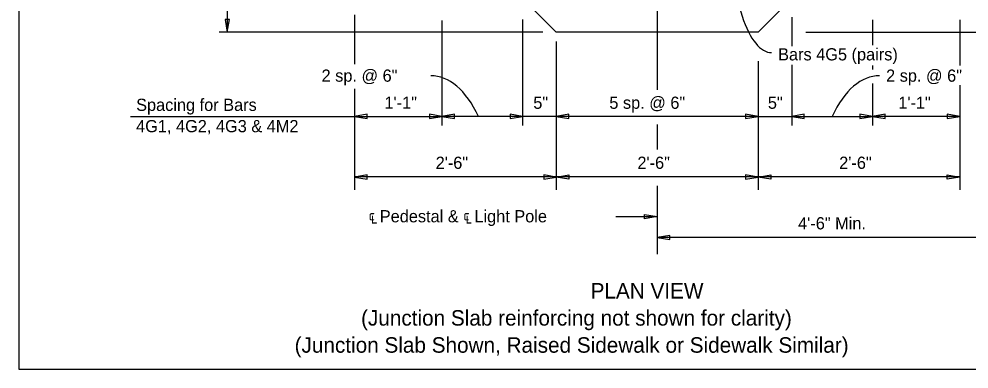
# Model space of a CAD drawing. Extents: x 0 to 54.1, y -0.5 to 22.5.
# Drawn here: x 0.01 to 11.78, y 1.54 to 5.88 of the extents above; entities that cross this region are included whole.
import ezdxf

# ---------------------------------------------------------------- set-up
doc = ezdxf.new("R2010")
doc.units = 0
for name, color, linetype in [('ActivePts-ConstElements', 7, 'Continuous'), ('CL_Major', 7, 'Continuous'), ('Dimension', 7, 'Continuous'), ('TextStructures', 7, 'Continuous'), ('WallConc', 7, 'Continuous')]:
    doc.layers.add(name, color=color, linetype=linetype)

msp = doc.modelspace()

# ---------------------------------------------------------------- linework, layer by layer
at = {"layer": 'ActivePts-ConstElements'}
msp.add_lwpolyline([(0.012, 1.54), (30.8, 1.54), (30.8, 21), (0.012, 21)], close=True, dxfattribs=at)
at = {"layer": 'CL_Major'}
for p, q in [((7.919, 15.044), (7.919, 5.002)), ((7.919, 4.572), (7.919, 4.26)), ((7.919, 3.812), (7.919, 2.962))]:
    msp.add_line(p, q, dxfattribs=at)
at = {"layer": 'Dimension'}
for p, q in [((2.593, 6.841), (2.593, 5.716)), ((4.169, 5.931), (4.169, 5.319)), ((9.586, 5.9), (9.586, 5.543)), ((5.252, 5.861), (5.252, 4.558)), ((6.252, 5.874), (6.252, 4.558)), ((10.586, 5.867), (10.586, 5.554)), ((11.669, 5.867), (11.669, 5.303)), ((6.503, 5.716), (2.493, 5.716)), ((9.762, 5.716), (15.801, 5.716)), ((6.669, 5.6), (6.669, 3.759)), ((9.169, 5.357), (9.169, 3.759)), ((9.586, 5.311), (9.586, 4.558)), ((10.586, 5.3), (10.586, 5.252)), ((10.586, 5.08), (10.586, 4.558)), ((4.169, 5.013), (4.169, 3.759)), ((11.669, 5.06), (11.669, 3.759)), ((1.394, 4.671), (4.169, 4.671)), ((4.169, 4.671), (5.252, 4.671)), ((6.252, 4.671), (5.252, 4.671)), ((6.669, 4.671), (6.252, 4.671)), ((9.169, 4.671), (6.669, 4.671)), ((9.169, 4.671), (9.586, 4.671)), ((9.586, 4.671), (10.586, 4.671)), ((11.669, 4.671), (10.586, 4.671)), ((11.669, 3.921), (4.169, 3.921)), ((7.408, 3.43), (7.919, 3.43)), ((12.419, 3.171), (7.919, 3.171))]:
    msp.add_line(p, q, dxfattribs=at)
for points in [[(2.593, 5.716), (2.619, 5.872), (2.566, 5.872)], [(4.169, 4.671), (4.325, 4.644), (4.325, 4.697)], [(5.252, 4.671), (5.096, 4.697), (5.096, 4.644)], [(5.252, 4.671), (5.409, 4.644), (5.409, 4.697)], [(6.252, 4.671), (6.096, 4.697), (6.096, 4.644)], [(6.669, 4.671), (6.825, 4.644), (6.825, 4.697)], [(9.169, 4.671), (9.013, 4.697), (9.013, 4.644)], [(9.586, 4.671), (9.742, 4.644), (9.742, 4.697)], [(10.586, 4.671), (10.43, 4.697), (10.43, 4.644)], [(10.586, 4.671), (10.742, 4.644), (10.742, 4.697)], [(11.669, 4.671), (11.513, 4.697), (11.513, 4.644)], [(4.169, 3.92), (4.325, 3.894), (4.325, 3.947)], [(6.669, 3.92), (6.513, 3.947), (6.513, 3.894)], [(6.669, 3.92), (6.825, 3.947), (6.825, 3.894)], [(9.169, 3.92), (9.013, 3.947), (9.013, 3.894)], [(9.169, 3.92), (9.326, 3.947), (9.326, 3.894)], [(11.669, 3.92), (11.513, 3.894), (11.513, 3.947)], [(7.919, 3.43), (7.763, 3.403), (7.763, 3.456)], [(7.919, 3.171), (8.075, 3.144), (8.075, 3.197)]]:
    msp.add_lwpolyline(points, close=True, dxfattribs=at)
for centre, major_axis, ratio, start_param, end_param in [((9.293, 6.768), (-0.043, 1.305), 0.351657, 1.406981, 3.141593), ((5.154, 3.767), (0.039, -1.406), 0.527049, 2.254078, 3.141628), ((10.636, 3.767), (-0.039, -1.406), 0.527049, 3.141557, 4.029108)]:
    msp.add_ellipse(centre, major_axis=major_axis, ratio=ratio, start_param=start_param, end_param=end_param, dxfattribs=at)
at = {"layer": 'WallConc'}
for p, q in [((4.169, 8.216), (6.669, 5.716)), ((11.669, 8.216), (9.169, 5.716)), ((9.169, 5.716), (6.669, 5.716))]:
    msp.add_line(p, q, dxfattribs=at)

# ---------------------------------------------------------------- texts
at = {"layer": 'Dimension'}
for s, height, p in [('Spacing for Bars', 0.1512, (1.463, 4.739)), ('4G1, 4G2, 4G3 & 4M2', 0.1512, (1.463, 4.475)), ('PLAN VIEW', 0.192, (7.094, 2.414)), ('(Junction Slab reinforcing not shown for clarity)', 0.192, (4.25, 2.078)), ('(Junction Slab Shown, Raised Sidewalk or Sidewalk Similar)', 0.192, (3.427, 1.742))]:
    msp.add_text(s, height=height, dxfattribs=at).set_placement(p)
at = {"layer": 'TextStructures'}
for s, p in [('Bars 4G5 (pairs)', (9.417, 5.365)), ('2 sp. @ 6"', (3.761, 5.101)), ('2 sp. @ 6"', (10.755, 5.101)), ('1\'-1"', (4.54, 4.765)), ('5"', (6.384, 4.765)), ('5 sp. @ 6"', (7.326, 4.765)), ('5"', (9.29, 4.765)), ('1\'-1"', (10.906, 4.765)), ('2\'-6"', (5.174, 4.021)), ('2\'-6"', (7.674, 4.021)), ('2\'-6"', (10.174, 4.021)), ('℄ Pedestal & ℄ Light Pole', (4.344, 3.358)), ('4\'-6" Min.', (9.665, 3.271))]:
    msp.add_text(s, height=0.1512, dxfattribs=at).set_placement(p)

doc.saveas('drawing.dxf')
